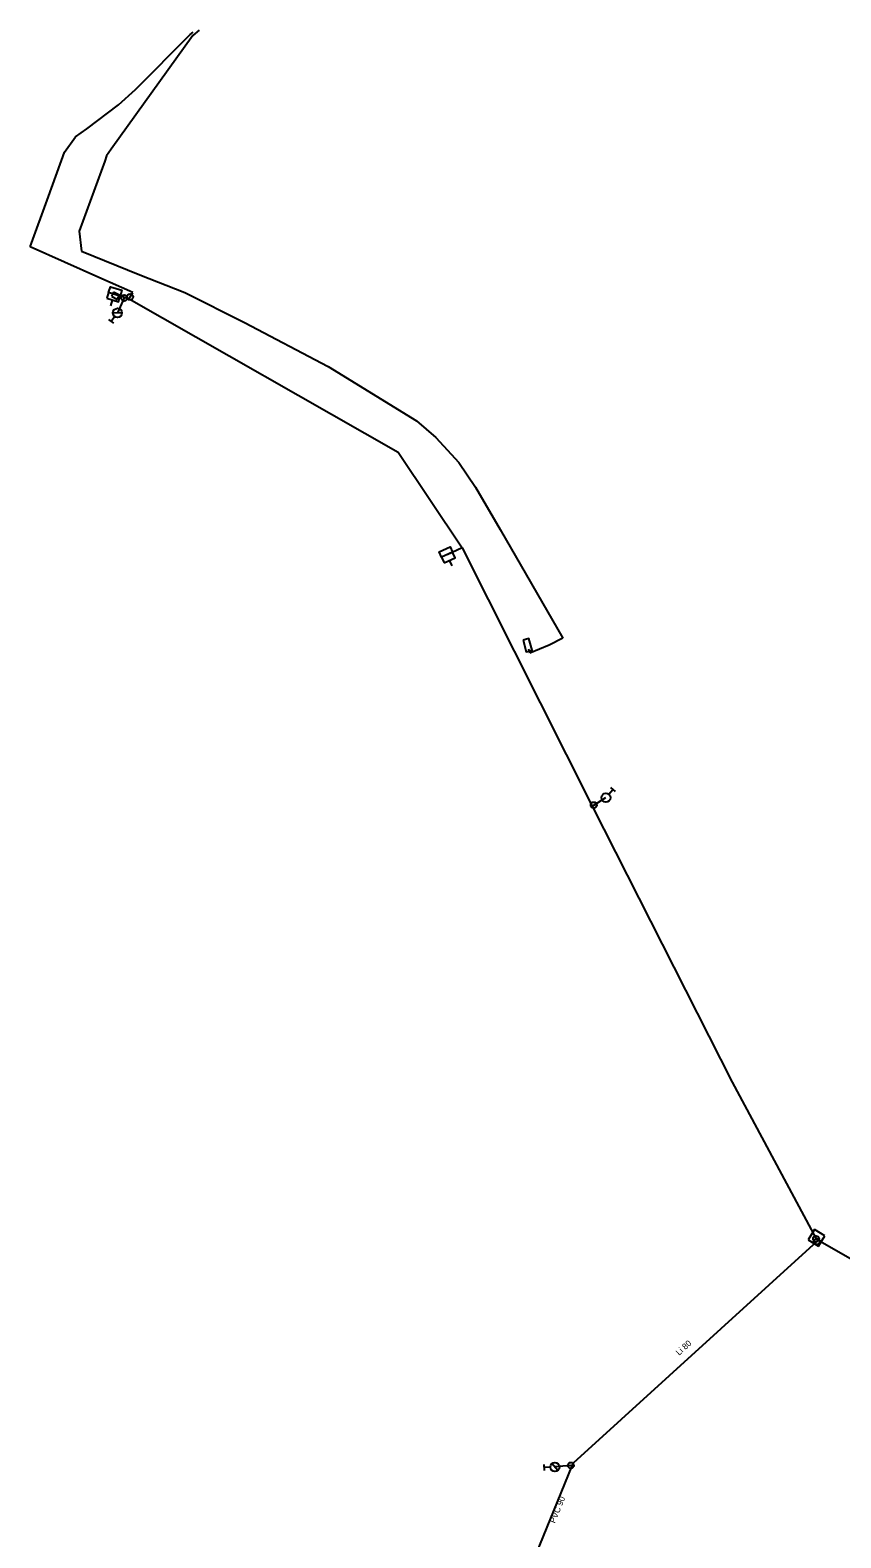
# Model space of a CAD drawing. Extents: x -701133 to -700495, y -1142806 to -1142020.
# Drawn here: x -700860.7 to -700726.5, y -1142269.2 to -1142019.9 of the extents above; entities that cross this region are included whole.
import ezdxf

# ---------------------------------------------------------------- set-up
doc = ezdxf.new("R2010")
doc.units = 0
doc.layers.add('Level 0', color=7, linetype='Continuous')

msp = doc.modelspace()

# ---------------------------------------------------------------- linework, layer by layer
at = {"layer": 'Level 0'}
for p, q in [((-700834.17, -1142020.69), (-700833.68, -1142020.3)), ((-700832.68, -1142019.95), (-700833.73, -1142020.83)), ((-700833.73, -1142020.83), (-700847.24, -1142039.64)), ((-700843.22, -1142029.78), (-700834.17, -1142020.69)), ((-700846.01, -1142032.3), (-700843.22, -1142029.78)), ((-700851.27, -1142036.25), (-700846.01, -1142032.3)), ((-700854.99, -1142040.14), (-700853.14, -1142037.58)), ((-700853.14, -1142037.58), (-700851.27, -1142036.25)), ((-700857.6, -1142047.43), (-700854.99, -1142040.14)), ((-700847.24, -1142039.64), (-700847.99, -1142040.73)), ((-700848.27, -1142041.63), (-700852.52, -1142053.19)), ((-700847.99, -1142040.73), (-700848.27, -1142041.63)), ((-700860.65, -1142055.75), (-700857.6, -1142047.43)), ((-700852.52, -1142053.19), (-700852.16, -1142056.47)), ((-700849.28, -1142060.83), (-700860.65, -1142055.75)), ((-700852.16, -1142056.47), (-700842.5, -1142060.4)), ((-700843.66, -1142063.33), (-700849.28, -1142060.83)), ((-700842.5, -1142060.4), (-700835.03, -1142063.32)), ((-700847.29, -1142065.53), (-700847, -1142064.58)), ((-700846.85, -1142063.26), (-700847.21, -1142063.95)), ((-700847.21, -1142063.95), (-700846.23, -1142064.47)), ((-700845.87, -1142063.78), (-700846.85, -1142063.26)), ((-700845.05, -1142064.13), (-700846.7, -1142063.62)), ((-700846.23, -1142064.47), (-700845.87, -1142063.78)), ((-700845.09, -1142064.23), (-700846.2, -1142066.69)), ((-700845.05, -1142064.13), (-700845.09, -1142064.23)), ((-700844.26, -1142064.38), (-700845.05, -1142064.13)), ((-700844.26, -1142064.38), (-700844.11, -1142064.06)), ((-700844.26, -1142064.38), (-700799.73, -1142089.7)), ((-700844.11, -1142064.06), (-700843.66, -1142063.33)), ((-700835.03, -1142063.32), (-700825.18, -1142068.29)), ((-700846.64, -1142067.3), (-700847.23, -1142068.11)), ((-700845.45, -1142066.66), (-700846.95, -1142066.72)), ((-700846.82, -1142068.4), (-700847.63, -1142067.81)), ((-700825.18, -1142068.29), (-700811.34, -1142075.57)), ((-700811.34, -1142075.57), (-700796.71, -1142084.55)), ((-700796.71, -1142084.55), (-700793.55, -1142087.31)), ((-700793.55, -1142087.31), (-700789.71, -1142091.45)), ((-700799.73, -1142089.7), (-700789.19, -1142105.56)), ((-700789.71, -1142091.45), (-700786.96, -1142095.53)), ((-700786.96, -1142095.53), (-700782.88, -1142102.52)), ((-700782.88, -1142102.52), (-700772.52, -1142120.48)), ((-700789.19, -1142105.56), (-700791.66, -1142106.67)), ((-700790.84, -1142108.49), (-700791.25, -1142107.58)), ((-700789.19, -1142105.56), (-700767.68, -1142148.24)), ((-700777.97, -1142122.95), (-700778.15, -1142122.27)), ((-700774.8, -1142121.62), (-700777.97, -1142122.95)), ((-700772.52, -1142120.48), (-700774.8, -1142121.62)), ((-700767.4, -1142148.06), (-700765.39, -1142146.83)), ((-700764.9, -1142146.26), (-700764.26, -1142145.5)), ((-700764.64, -1142145.17), (-700763.88, -1142145.82)), ((-700767.68, -1142148.24), (-700767.4, -1142148.06)), ((-700767.68, -1142148.24), (-700744.49, -1142193.9)), ((-700744.49, -1142193.9), (-700730.62, -1142219.77)), ((-700730.85, -1142218.21), (-700731.9, -1142219.92)), ((-700729.14, -1142219.26), (-700730.85, -1142218.21)), ((-700730.62, -1142219.77), (-700730.31, -1142219.96)), ((-700730.19, -1142220.97), (-700729.14, -1142219.26)), ((-700730.49, -1142220.23), (-700770.82, -1142256.84)), ((-700731.9, -1142219.92), (-700730.19, -1142220.97)), ((-700730.31, -1142219.96), (-700730.49, -1142220.23)), ((-700730.31, -1142219.96), (-700722.72, -1142224.3)), ((-700775.55, -1142258.08), (-700775.6, -1142257.08)), ((-700773.34, -1142258.05), (-700774.32, -1142256.92)), ((-700770.82, -1142256.84), (-700771.02, -1142257.29)), ((-700771.02, -1142257.29), (-700783.41, -1142287.64)), ((-700774.58, -1142257.53), (-700775.58, -1142257.58)), ((-700771.19, -1142257.24), (-700773.83, -1142257.49)), ((-700771.02, -1142257.29), (-700771.19, -1142257.24))]:
    msp.add_line(p, q, dxfattribs=at)
for points in [[(-700847.66, -1142063.32), (-700847.36, -1142062.37), (-700845.45, -1142062.96), (-700845.74, -1142063.92)], [(-700792.57, -1142107.08), (-700792.98, -1142106.17), (-700791.16, -1142105.35), (-700790.75, -1142106.26)]]:
    msp.add_lwpolyline(points, dxfattribs=at)
for points in [[(-700847.95, -1142064.28), (-700846.04, -1142064.87), (-700845.74, -1142063.92), (-700847.66, -1142063.32)], [(-700792.16, -1142107.99), (-700790.34, -1142107.17), (-700790.75, -1142106.26), (-700792.57, -1142107.08)], [(-700779.09, -1142120.79), (-700778.58, -1142122.72), (-700777.61, -1142122.47), (-700778.12, -1142120.54)]]:
    msp.add_lwpolyline(points, close=True, dxfattribs=at)
for centre, radius in [((-700845.09, -1142064.23), 0.5), ((-700844.11, -1142064.06), 0.5), ((-700846.2, -1142066.69), 0.75), ((-700765.39, -1142146.83), 0.75), ((-700767.4, -1142148.06), 0.5), ((-700730.62, -1142219.77), 0.5), ((-700730.49, -1142220.23), 0.5), ((-700773.83, -1142257.49), 0.75), ((-700771.19, -1142257.24), 0.5)]:
    msp.add_circle(centre, radius, dxfattribs=at)

# ---------------------------------------------------------------- texts
for s, rotation, p in [('Li 80', 42.232, (-700753.28, -1142239.12)), ('PVC 90', 68.165, (-700773.81, -1142266.88))]:
    msp.add_text(s, height=1, rotation=rotation, dxfattribs=at).set_placement(p)

doc.saveas('drawing.dxf')
